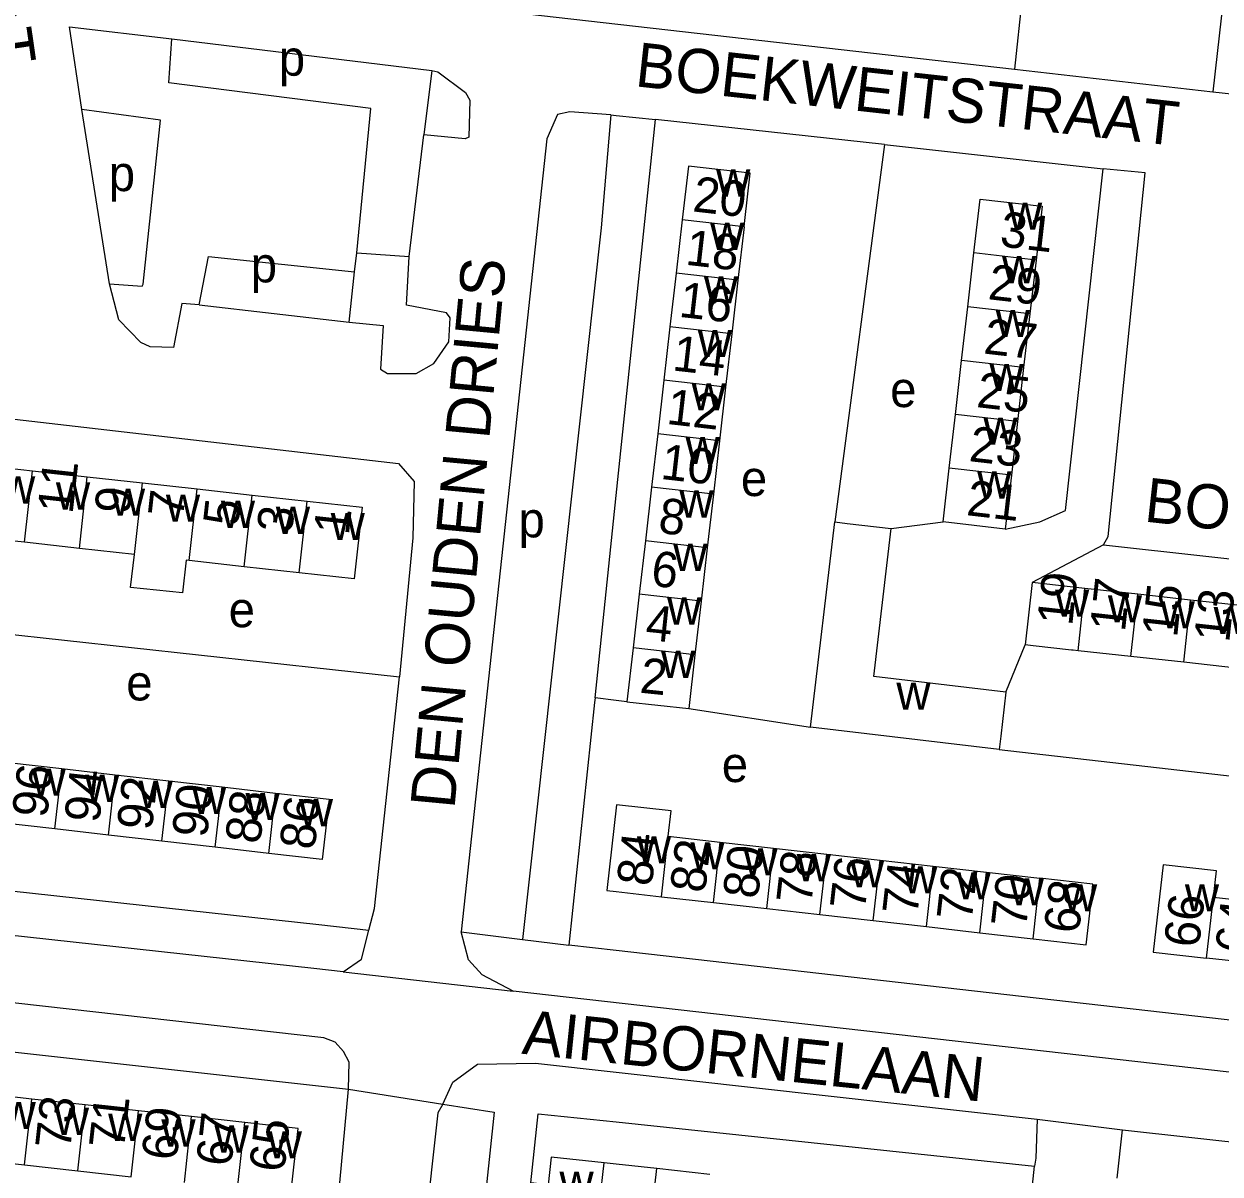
# Model space of a CAD drawing. Extents: x 161936 to 163647, y 386450 to 388633.
# Drawn here: x 162533 to 162668.3, y 387350.8 to 387480.8 of the extents above; entities that cross this region are included whole.
import ezdxf

# ---------------------------------------------------------------- set-up
doc = ezdxf.new("R2010")
doc.units = 0
for name, color, linetype in [('BLT_Basislijn', 7, 'Continuous'), ('BLT_Bebouwing', 7, 'Continuous'), ('BLT_Centroide', 7, 'Continuous'), ('BLT_Huisnummer', 7, 'Continuous'), ('BLT_Huisnummer_ tussenligend', 7, 'Continuous'), ('BLT_Onderverdeling_panden', 7, 'Continuous'), ('BLT_Straatnaam', 7, 'Continuous'), ('BLT_Vlakafsluiter', 7, 'Continuous')]:
    doc.layers.add(name, color=color, linetype=linetype)

msp = doc.modelspace()

# ---------------------------------------------------------------- linework, layer by layer
at = {"layer": 'BLT_Basislijn'}
for p, q in [((162670.29, 387498.35), (162667.46, 387473.15)), ((162545.8, 387487), (162645.04, 387475.7)), ((162549.76, 387479.15), (162579.17, 387475.55)), ((162579.17, 387475.55), (162578.27, 387468.3)), ((162645.04, 387475.7), (162667.46, 387473.15)), ((162667.46, 387473.15), (162672.44, 387472.59)), ((162542.71, 387451.45), (162539.58, 387471.14)), ((162630.32, 387467.21), (162604.44, 387470)), ((162576.59, 387454.52), (162578.27, 387468.3)), ((162630.32, 387467.21), (162624.71, 387424.51)), ((162630.32, 387467.21), (162655.05, 387464.44)), ((162570.42, 387452.81), (162570.68, 387454.96)), ((162570.68, 387454.96), (162576.59, 387454.52)), ((162569.82, 387447.12), (162570.42, 387452.81)), ((162552.85, 387449.08), (162569.82, 387447.12)), ((162631.1, 387423.76), (162636.96, 387424.52)), ((162655.11, 387421.92), (162647.05, 387417.66)), ((162520.54, 387413.01), (162575.5, 387406.98)), ((162644.06, 387405.25), (162646.25, 387410.6)), ((162608.21, 387403.43), (162621.97, 387401.29)), ((162643.3, 387398.77), (162704.64, 387391.8)), ((162582.46, 387378.17), (162589.42, 387377.28)), ((162589.42, 387377.28), (162594.64, 387376.67)), ((162710.05, 387357.7), (162588.35, 387371.46)), ((162514.47, 387366.54), (162569.73, 387360.37)), ((162567.63, 387337.74), (162569.73, 387360.37)), ((162656.65, 387350.3), (162657.23, 387355.77)), ((162644.82, 387328.18), (162647.28, 387351.66))]:
    msp.add_line(p, q, dxfattribs=at)
for points in [[(162648.95, 387510.13), (162646.83, 387491.72), (162645.91, 387483.89), (162645.04, 387475.7)], [(162539.58, 387471.14), (162538.18, 387480.49), (162549.76, 387479.15)], [(162570.68, 387454.96), (162572.28, 387471.27), (162549.42, 387474.18), (162549.76, 387479.15)], [(162579.17, 387475.55), (162579.85, 387475.39), (162582.97, 387473.07), (162583.44, 387472.19), (162583.33, 387468.01), (162582.92, 387467.82), (162578.27, 387468.3)], [(162542.71, 387451.45), (162546.42, 387451.18), (162546.51, 387451.4), (162548.49, 387469.96), (162539.58, 387471.14)], [(162599.41, 387470.54), (162594.75, 387470.87), (162593.35, 387470.57), (162592.17, 387467.82), (162582.46, 387378.17)], [(162599.41, 387470.54), (162598.31, 387457.76), (162589.42, 387377.28)], [(162597.61, 387404.62), (162600, 387427.52), (162604.44, 387470)], [(162599.41, 387470.54), (162600, 387470.47), (162604.44, 387470)], [(162643.98, 387423.71), (162647.9, 387424.51), (162650.82, 387425.82), (162655.05, 387464.44)], [(162655.11, 387421.92), (162655.64, 387422.87), (162659.8, 387464), (162655.05, 387464.44)], [(162552.85, 387449.08), (162553.92, 387454.52), (162570.42, 387452.81)], [(162569.82, 387447.12), (162573.64, 387446.72), (162573.37, 387441.79), (162574.15, 387441.31), (162577.38, 387441.31), (162579.37, 387442.42), (162581.07, 387444.87), (162581.22, 387447.58), (162580.83, 387448.16), (162576.28, 387449.01), (162576.59, 387454.52)], [(162552.85, 387449.08), (162550.91, 387449.22), (162549.96, 387444.23), (162547.31, 387444.33), (162546.26, 387444.81), (162543.76, 387447.36), (162542.71, 387451.45)], [(162529.01, 387436.47), (162575.39, 387431.12), (162577.18, 387429.08), (162577, 387422.72), (162575.5, 387406.98)], [(162655.11, 387421.92), (162715.68, 387415.23), (162718.03, 387414.06), (162718.96, 387410.77), (162718.89, 387410.16), (162718.85, 387408.89)], [(162572.04, 387378.34), (162572.68, 387380.82), (162575.5, 387406.98)], [(162597.61, 387404.62), (162597.55, 387404.08), (162594.64, 387376.67)], [(162601.22, 387404.16), (162600, 387404.32), (162597.61, 387404.62)], [(162569.15, 387373.63), (162565.82, 387374.01), (162518.6, 387379.19), (162500.21, 387381.23), (162492.75, 387382.01), (162486.36, 387383.07), (162454.3, 387390.72)], [(162517.61, 387384.33), (162519.15, 387384.16), (162566.37, 387378.98), (162572.04, 387378.34)], [(162569.15, 387373.63), (162571.19, 387375.07), (162572.04, 387378.34)], [(162588.35, 387371.46), (162584.86, 387373.31), (162583.3, 387375.01), (162582.46, 387378.17)], [(162709.16, 387363.93), (162705.92, 387364.03), (162600, 387376.06), (162594.64, 387376.67)], [(162566.96, 387366.19), (162515.01, 387372.02)], [(162569.73, 387360.37), (162569.8, 387363.41), (162569.19, 387364.64), (162568.23, 387365.7), (162566.96, 387366.19)], [(162580.39, 387358.66), (162581.53, 387361.15), (162584.32, 387363.19)], [(162584.32, 387363.19), (162590.89, 387363.33), (162600, 387362.31), (162647.61, 387356.97)], [(162580.39, 387358.66), (162579.85, 387357.68), (162570.59, 387274.37)], [(162580.39, 387358.66), (162586.2, 387357.76), (162577.32, 387273.64)], [(162590.36, 387349.77), (162591.19, 387357.6), (162600, 387356.67), (162647.28, 387351.66)], [(162647.61, 387356.97), (162647.45, 387352.58), (162647.28, 387351.66)], [(162657.23, 387355.77), (162712.78, 387349.62)]]:
    msp.add_lwpolyline(points, dxfattribs=at)
at = {"layer": 'BLT_Bebouwing'}
for p, q in [((162607.47, 387458.69), (162606.78, 387452.64)), ((162614.46, 387457.89), (162613.76, 387451.84)), ((162639.75, 387448.85), (162640.45, 387454.93)), ((162647.47, 387454.13), (162646.77, 387448.05)), ((162606.78, 387452.64), (162606.08, 387446.59)), ((162613.76, 387451.84), (162613.07, 387445.79)), ((162639.06, 387442.77), (162639.75, 387448.85)), ((162646.77, 387448.05), (162646.07, 387441.96)), ((162606.08, 387446.59), (162605.39, 387440.54)), ((162613.07, 387445.79), (162612.37, 387439.74)), ((162638.36, 387436.68), (162639.06, 387442.77)), ((162646.07, 387441.96), (162645.37, 387435.88)), ((162605.39, 387440.54), (162604.7, 387434.49)), ((162612.37, 387439.74), (162611.68, 387433.69)), ((162637.66, 387430.6), (162638.36, 387436.68)), ((162645.37, 387435.88), (162644.68, 387429.79)), ((162604.7, 387434.49), (162604, 387428.44)), ((162611.68, 387433.69), (162610.99, 387427.64)), ((162527.79, 387430.99), (162534, 387430.3)), ((162534, 387430.3), (162540.21, 387429.61)), ((162540.21, 387429.61), (162546.43, 387428.92)), ((162636.96, 387424.52), (162637.66, 387430.6)), ((162644.68, 387429.79), (162643.98, 387423.71)), ((162546.43, 387428.92), (162552.64, 387428.24)), ((162552.64, 387428.24), (162558.86, 387427.55)), ((162604, 387428.44), (162603.31, 387422.39)), ((162558.86, 387427.55), (162565.07, 387426.86)), ((162610.99, 387427.64), (162610.29, 387421.59)), ((162621.97, 387401.29), (162624.71, 387424.51)), ((162643.98, 387423.71), (162636.96, 387424.52)), ((162533.11, 387422.21), (162526.89, 387422.89)), ((162539.32, 387421.52), (162533.11, 387422.21)), ((162545.53, 387420.83), (162539.32, 387421.52)), ((162603.31, 387422.39), (162602.61, 387416.34)), ((162610.29, 387421.59), (162609.6, 387415.54)), ((162557.96, 387419.45), (162551.74, 387420.14)), ((162564.17, 387418.76), (162557.96, 387419.45)), ((162647.05, 387417.66), (162646.25, 387410.6)), ((162652.99, 387417), (162647.05, 387417.66)), ((162602.61, 387416.34), (162601.92, 387410.29)), ((162658.97, 387416.34), (162652.99, 387417)), ((162664.94, 387415.67), (162658.97, 387416.34)), ((162609.6, 387415.54), (162608.9, 387409.49)), ((162670.91, 387415.01), (162664.94, 387415.67)), ((162601.92, 387410.29), (162601.22, 387404.16)), ((162608.9, 387409.49), (162608.21, 387403.43)), ((162658.2, 387409.3), (162652.23, 387409.95)), ((162664.17, 387408.65), (162658.2, 387409.3)), ((162670.15, 387407.99), (162664.17, 387408.65)), ((162601.22, 387404.16), (162608.21, 387403.43)), ((162643.3, 387398.77), (162621.97, 387401.29)), ((162531.28, 387397.31), (162537.32, 387396.62)), ((162537.32, 387396.62), (162543.37, 387395.93)), ((162543.37, 387395.93), (162549.41, 387395.24)), ((162549.41, 387395.24), (162555.46, 387394.55)), ((162555.46, 387394.55), (162561.5, 387393.86)), ((162536.54, 387389.8), (162530.5, 387390.49)), ((162542.59, 387389.11), (162536.54, 387389.8)), ((162548.63, 387388.42), (162542.59, 387389.11)), ((162605.89, 387388.97), (162611.77, 387388.31)), ((162554.68, 387387.73), (162548.63, 387388.42)), ((162560.72, 387387.04), (162554.68, 387387.73)), ((162617.79, 387387.63), (162623.81, 387386.95)), ((162623.81, 387386.95), (162629.83, 387386.27)), ((162629.83, 387386.27), (162635.85, 387385.59)), ((162635.85, 387385.59), (162641.88, 387384.91)), ((162641.88, 387384.91), (162647.9, 387384.23)), ((162605.12, 387382.13), (162610.99, 387381.47)), ((162667.54, 387382.09), (162673.58, 387381.41)), ((162610.99, 387381.47), (162617.02, 387380.79)), ((162617.02, 387380.79), (162623.04, 387380.11)), ((162623.04, 387380.11), (162629.06, 387379.43)), ((162629.06, 387379.43), (162635.08, 387378.75)), ((162635.08, 387378.75), (162641.1, 387378.07)), ((162641.1, 387378.07), (162647.13, 387377.39)), ((162672.8, 387374.51), (162666.75, 387375.19)), ((162533.94, 387359.26), (162527.92, 387359.92)), ((162539.96, 387358.59), (162533.94, 387359.26)), ((162545.98, 387357.93), (162539.96, 387358.59)), ((162552, 387357.27), (162545.98, 387357.93)), ((162558.02, 387356.6), (162552, 387357.27)), ((162527.1, 387352.47), (162533.12, 387351.8)), ((162533.12, 387351.8), (162539.14, 387351.14)), ((162539.14, 387351.14), (162545.16, 387350.48)), ((162610.58, 387350.73), (162604.61, 387351.39))]:
    msp.add_line(p, q, dxfattribs=at)
for points in [[(162614.46, 387457.89), (162614.54, 387458.59), (162615.15, 387463.94), (162608.17, 387464.74), (162607.47, 387458.69)], [(162640.45, 387454.93), (162641.15, 387461.02), (162648.16, 387460.21), (162647.47, 387454.13)], [(162565.07, 387426.86), (162571.27, 387426.17), (162570.38, 387418.08), (162564.17, 387418.76)], [(162624.71, 387424.51), (162626.13, 387424.34), (162631.1, 387423.76)], [(162644.06, 387405.25), (162629.12, 387407.02), (162631.1, 387423.76)], [(162551.74, 387420.14), (162551.37, 387420.18), (162550.96, 387416.51), (162545.1, 387417.11), (162545.53, 387420.83)], [(162652.23, 387409.95), (162651.66, 387410.01), (162651.49, 387410.03), (162647.13, 387410.5), (162646.25, 387410.6)], [(162644.06, 387405.25), (162643.48, 387400.29), (162643.3, 387398.77)], [(162561.5, 387393.86), (162567.54, 387393.17), (162566.76, 387386.35), (162560.72, 387387.04)], [(162605.89, 387388.97), (162606.21, 387391.84), (162600.05, 387392.54), (162598.95, 387382.83), (162600, 387382.71), (162605.12, 387382.13)], [(162611.77, 387388.31), (162617.79, 387387.63)], [(162667.54, 387382.09), (162667.88, 387385.07), (162661.83, 387385.75), (162660.71, 387375.88), (162666.75, 387375.19)], [(162647.13, 387377.39), (162653.14, 387376.71), (162653.65, 387381.25), (162653.91, 387383.55), (162647.9, 387384.23)], [(162557.19, 387349.15), (162563.21, 387348.49), (162564.03, 387355.94), (162558.02, 387356.6)], [(162598.64, 387352.04), (162592.65, 387352.7), (162592.3, 387349.55), (162590.36, 387349.77)], [(162604.61, 387351.39), (162600, 387351.89), (162598.64, 387352.04)]]:
    msp.add_lwpolyline(points, dxfattribs=at)
at = {"layer": 'BLT_Onderverdeling_panden'}
for p, q in [((162614.46, 387457.89), (162607.47, 387458.69)), ((162647.47, 387454.13), (162640.45, 387454.93)), ((162613.76, 387451.84), (162606.78, 387452.64)), ((162646.77, 387448.05), (162639.75, 387448.85)), ((162613.07, 387445.79), (162606.08, 387446.59)), ((162646.07, 387441.96), (162639.06, 387442.77)), ((162612.37, 387439.74), (162605.39, 387440.54)), ((162645.37, 387435.88), (162638.36, 387436.68)), ((162611.68, 387433.69), (162604.7, 387434.49)), ((162533.11, 387422.21), (162534, 387430.3)), ((162539.32, 387421.52), (162540.21, 387429.61)), ((162644.68, 387429.79), (162637.66, 387430.6)), ((162545.53, 387420.83), (162546.43, 387428.92)), ((162551.74, 387420.14), (162552.64, 387428.24)), ((162610.99, 387427.64), (162604, 387428.44)), ((162557.96, 387419.45), (162558.86, 387427.55)), ((162564.17, 387418.76), (162565.07, 387426.86)), ((162610.29, 387421.59), (162603.31, 387422.39)), ((162609.6, 387415.54), (162602.61, 387416.34)), ((162652.23, 387409.95), (162652.99, 387417)), ((162658.2, 387409.3), (162658.97, 387416.34)), ((162664.17, 387408.65), (162664.94, 387415.67)), ((162608.9, 387409.49), (162601.92, 387410.29)), ((162536.54, 387389.8), (162537.32, 387396.62)), ((162542.59, 387389.11), (162543.37, 387395.93)), ((162548.63, 387388.42), (162549.41, 387395.24)), ((162554.68, 387387.73), (162555.46, 387394.55)), ((162560.72, 387387.04), (162561.5, 387393.86)), ((162605.12, 387382.13), (162605.89, 387388.97)), ((162610.99, 387381.47), (162611.77, 387388.31)), ((162617.02, 387380.79), (162617.79, 387387.63)), ((162623.04, 387380.11), (162623.81, 387386.95)), ((162629.06, 387379.43), (162629.83, 387386.27)), ((162635.08, 387378.75), (162635.85, 387385.59)), ((162641.1, 387378.07), (162641.88, 387384.91)), ((162647.13, 387377.39), (162647.9, 387384.23)), ((162666.75, 387375.19), (162667.54, 387382.09)), ((162533.12, 387351.8), (162533.94, 387359.26)), ((162539.14, 387351.14), (162539.96, 387358.59)), ((162545.16, 387350.48), (162545.98, 387357.93)), ((162551.18, 387349.81), (162552, 387357.27)), ((162557.19, 387349.15), (162558.02, 387356.6)), ((162597.65, 387343.25), (162598.64, 387352.04)), ((162603.62, 387342.6), (162604.61, 387351.39))]:
    msp.add_line(p, q, dxfattribs=at)
at = {"layer": 'BLT_Vlakafsluiter'}
for p, q in [((162569.15, 387373.63), (162588.35, 387371.46)), ((162569.73, 387360.37), (162580.39, 387358.66)), ((162647.61, 387356.97), (162657.23, 387355.77))]:
    msp.add_line(p, q, dxfattribs=at)

# ---------------------------------------------------------------- texts
at = {"layer": 'BLT_Centroide'}
for s, p in [('p', (162561.86, 387474.97)), ('p', (162542.63, 387461.92)), ('w', (162611.3, 387461.31)), ('w', (162644.3, 387457.56)), ('w', (162610.62, 387455.28)), ('p', (162558.68, 387451.6)), ('w', (162643.62, 387451.5)), ('w', (162609.92, 387449.22)), ('w', (162642.91, 387445.41)), ('w', (162609.23, 387443.16)), ('w', (162642.21, 387439.31)), ('w', (162608.54, 387437.12)), ('e', (162630.98, 387437.5)), ('w', (162641.52, 387433.25)), ('w', (162607.84, 387431.06)), ('w', (162530.45, 387426.59)), ('e', (162614.1, 387427.44)), ('w', (162640.82, 387427.16)), ('w', (162536.66, 387425.91)), ('w', (162542.88, 387425.22)), ('w', (162607.15, 387425)), ('w', (162549.09, 387424.53)), ('w', (162555.3, 387423.84)), ('w', (162561.52, 387423.16)), ('w', (162567.72, 387422.47)), ('p', (162588.96, 387422.77)), ('w', (162606.45, 387418.97)), ('w', (162605.76, 387412.91)), ('w', (162649.62, 387413.8)), ('w', (162655.59, 387413.16)), ('e', (162556.19, 387412.61)), ('w', (162661.56, 387412.48)), ('w', (162667.55, 387411.83)), ('w', (162605.07, 387406.88)), ('e', (162544.61, 387404.33)), ('w', (162631.68, 387403.27)), ('e', (162611.94, 387395.1)), ('w', (162533.91, 387393.55)), ('w', (162539.95, 387392.86)), ('w', (162546, 387392.17)), ('w', (162552.05, 387391.48)), ('w', (162558.09, 387390.8)), ('w', (162564.12, 387390.11)), ('w', (162602.34, 387385.91)), ('w', (162608.38, 387385.22)), ('w', (162614.39, 387384.55)), ('w', (162620.41, 387383.88)), ('w', (162626.44, 387383.19)), ('w', (162632.45, 387382.5)), ('w', (162638.48, 387381.83)), ('w', (162644.5, 387381.16)), ('w', (162650.52, 387380.47)), ('w', (162664.3, 387380.47)), ('w', (162530.52, 387355.86)), ('w', (162536.53, 387355.2)), ('w', (162542.56, 387354.53)), ('w', (162548.58, 387353.88)), ('w', (162554.59, 387353.2)), ('w', (162560.61, 387352.55)), ('w', (162593.59, 387347.97))]:
    msp.add_text(s, height=4, dxfattribs=at).set_placement(p)
at = {"layer": 'BLT_Huisnummer'}
for s, rotation, p in [('20', 353.4573, (162608.55, 387459.64)), ('31', 353.4556, (162643.28, 387455.68)), ('14', 353.4573, (162606.26, 387441.66)), ('25', 353.4636, (162640.65, 387437.51)), ('10', 353.4573, (162604.93, 387429.39)), ('9', 83.6831, (162544.97, 387425.31)), ('21', 353.4466, (162639.51, 387425.29)), ('5', 83.6761, (162557.25, 387423.94)), ('1', 83.6769, (162569.77, 387422.94)), ('6', 353.4573, (162603.83, 387417.32)), ('19', 83.7758, (162651.55, 387412.69)), ('13', 83.7762, (162669.3, 387410.8)), ('2', 354.0396, (162602.58, 387405.22)), ('94', 83.4939, (162541.56, 387390.4)), ('90', 83.4939, (162553.73, 387388.72)), ('86', 83.4949, (162565.9, 387387.36)), ('84', 83.5615, (162604.02, 387383.23)), ('80', 83.5605, (162616.02, 387381.81)), ('76', 83.5596, (162628.12, 387380.55)), ('72', 83.5587, (162640.19, 387379.32)), ('68', 83.567, (162652.31, 387377.88)), ('66', 83.5212, (162665.89, 387376.28)), ('73', 83.7071, (162538.27, 387353.46)), ('69', 83.7138, (162550.3, 387352.22)), ('65', 83.7079, (162562.47, 387350.9))]:
    msp.add_text(s, height=4, rotation=rotation, dxfattribs=at).set_placement(p)
at = {"layer": 'BLT_Huisnummer_ tussenligend'}
for s, rotation, p in [('18', 353.4573, (162607.74, 387453.61)), ('29', 353.4636, (162641.95, 387449.71)), ('16', 353.4573, (162607, 387447.72)), ('27', 353.4636, (162641.45, 387443.57)), ('12', 353.4573, (162605.6, 387435.61)), ('23', 353.4466, (162639.8, 387431.4)), ('11', 83.6831, (162538.54, 387425.34)), ('7', 83.6761, (162551.02, 387424.91)), ('8', 353.4573, (162604.66, 387423.3)), ('3', 83.6769, (162563.33, 387423.15)), ('17', 83.7762, (162657.52, 387412.01)), ('15', 83.7762, (162663.41, 387411.37)), ('4', 354.0396, (162603.22, 387411.2)), ('96', 83.4939, (162535.65, 387390.97)), ('92', 83.4939, (162547.5, 387389.55)), ('88', 83.4949, (162559.75, 387388.02)), ('82', 83.5605, (162610.05, 387382.48)), ('78', 83.5596, (162622.06, 387381.21)), ('74', 83.5587, (162634.05, 387379.96)), ('70', 83.567, (162646.34, 387378.53)), ('64', 83.5195, (162671.68, 387375.58)), ('71', 83.7138, (162544.35, 387353.51)), ('67', 83.7079, (162556.47, 387351.55))]:
    msp.add_text(s, height=4, rotation=rotation, dxfattribs=at).set_placement(p)
at = {"layer": 'BLT_Straatnaam'}
for s, rotation, p in [('BOEKWEITSTRAAT', 278.2054, (162520.68, 387536.97)), ('BOEKWEITSTRAAT', 353.6941, (162602.03, 387473.79)), ('DEN OUDEN DRIES', 84.6165, (162581.71, 387392)), ('BOEKWEITSTRAAT', 353.6941, (162659.59, 387424.57)), ('AIRBORNELAAN', 354.0501, (162589.25, 387364.39))]:
    msp.add_text(s, height=5, rotation=rotation, dxfattribs=at).set_placement(p)

doc.saveas('drawing.dxf')
